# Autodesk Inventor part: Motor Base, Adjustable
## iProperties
Title: Motor Base, Adjustable
Author: Robert D. LaBree
Shininess: 64.0
Angle Display Precision: 2
Document Length Units: 11272
Document Angle Units: 11286
Document Time Units: 11279
Document Mass Units: 11290
Document Length Units Precision: 3
Document Angle Units Precision: 2
Compacted: True
PropertySet Name: _Private Model Information
Created: 2001-10
Part Number: 56
Description: Dodge Adjustable NEMA Motor Base
Document SubType Name: Modeling
Designer: Robert D. LaBree
Control State: 0
Master: False
Checked Out: False
PropertySet Name: Design Tracking Control
Density: 0.0
Volumn: 0.0
Area: 0.0
PropertySet Name: Model Information
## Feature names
1. Extrusion1
2. Fillet1
3. Fillet2
4. Shell1
5. Extrusion2
6. Hole1
7. Extrusion3
8. Hole2
9. Extrusion4
